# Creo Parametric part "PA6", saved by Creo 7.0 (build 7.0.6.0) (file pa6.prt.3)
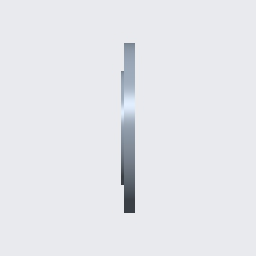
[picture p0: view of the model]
Units: Inch lbm Second (Pro/E Default); INCH, POUND, SECS

Created from: XX_INLBS_PART_SOLID_ABS.PRT

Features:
  1. datum plane "RIGHT"
  2. datum plane "TOP"
  3. datum plane "FRONT"
  4. coordinate system
  5. revolve "Revolve 1"
  6. pattern "Pattern 1"
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
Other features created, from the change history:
  hole "Hole 1" (2 times)
  pattern "Pattern 1"
  hole "Hole 1 [2]" (2 times)
  hole "Hole 1 [3]" (2 times)
  hole "Hole 1 [4]" (2 times)
  hole "Hole 2"
  pattern "Pattern 2"
  hole "Hole 2 [2]"
  hole "Hole 2 [3]"
  hole "Hole 2 [4]"
  hole "Hole 2 [5]"
  hole "Hole 2 [6]"
  chamfer "Chamfer 1"
  planar section "XSEC0001"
